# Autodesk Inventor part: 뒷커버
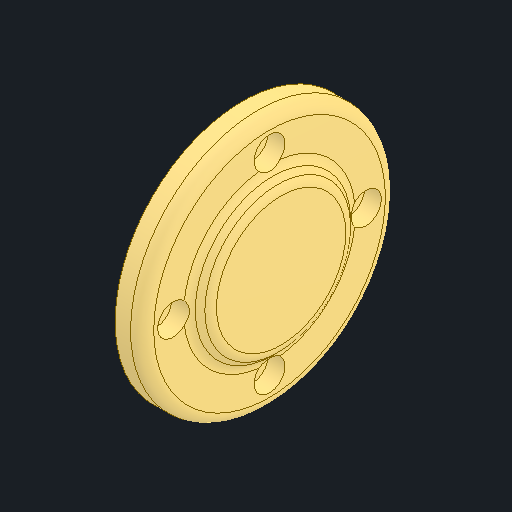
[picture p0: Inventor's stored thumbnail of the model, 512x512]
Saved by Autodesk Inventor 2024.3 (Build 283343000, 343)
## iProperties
Created: 2025-03
Part Number: 뒷커버
Material: 알루미늄 6061
Document SubType Name: Modeling
Designer: user
Density: 2.7 g/cm^3
Appearance: 기본값
Author: jhkim
Sending System: Autodesk Inventor 2025
Preprocessor: ST-DEVELOPER v20
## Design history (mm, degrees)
feature "솔리드1"
node "솔리드2"
